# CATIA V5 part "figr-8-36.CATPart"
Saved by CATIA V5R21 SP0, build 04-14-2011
Part number: Part1
Bounding box of the stored display mesh (mm): x -75 to 75, y -75 to 75, z 0 to 20
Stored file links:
  D:\CATIA V5R21 E-RESOURCES\CATIA-V5R21\catia-v5r21-prt\c08-catia-v5r20-prt\c08-catia-v5r21-figr-8-36.CATPart
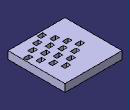
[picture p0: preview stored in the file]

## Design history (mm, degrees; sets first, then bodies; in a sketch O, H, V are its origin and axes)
Body1 (main body)
  Sketch1 on xy-plane, origin (0, 0, 0), H (1, 0, 0), V (0, 1, 0)
    line L1 (-75, 75) -> (75, 75)
    line L2 (75, 75) -> (75, -75)
    line L3 (75, -75) -> (-75, -75)
    line L4 (-75, -75) -> (-75, 75)
    axis line L5 (75, -75) -> (-75, 75)
    length L3 = 150
    length L2 = 150
    horizontal: L1 H, L3 H
    vertical: L2 V, L4 V
    midpoint: O L5
  Pad1: profile Sketch1, direction (0, 0, 1), length 20
  Sketch2 on face of Pad1, origin (0, 0, 20), H (1, 0, 0), V (0, 1, 0)
    line L1 (25, 40) -> (40, 40)
    line L2 (40, 40) -> (40, 30)
    line L3 (40, 30) -> (25, 30)
    line L4 (25, 30) -> (25, 40)
    reference projected line E1 (75, -75) -> (75, 75) from edge [face of Pad1 | face of Pad1]
    reference projected line E2 (75, 75) -> (-75, 75) from edge [face of Pad1 | face of Pad1]
    length L3 = 15
    length L4 = 10
    distance L2 E1 = 35
    distance L1 E2 = 35
    horizontal: L1 H, L3 H
    vertical: L2 V, L4 V
  Pocket1: profile Sketch2, direction (0, 0, -1), through (limit type 3)
  RectPattern1: of Pocket1, direction 1 instances 4, spacing 25, along edge [face of Pad1 | face of Pad1] reversed, direction 2 instances 4, spacing 25, along edge [face of Pad1 | face of Pad1], rotation -25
